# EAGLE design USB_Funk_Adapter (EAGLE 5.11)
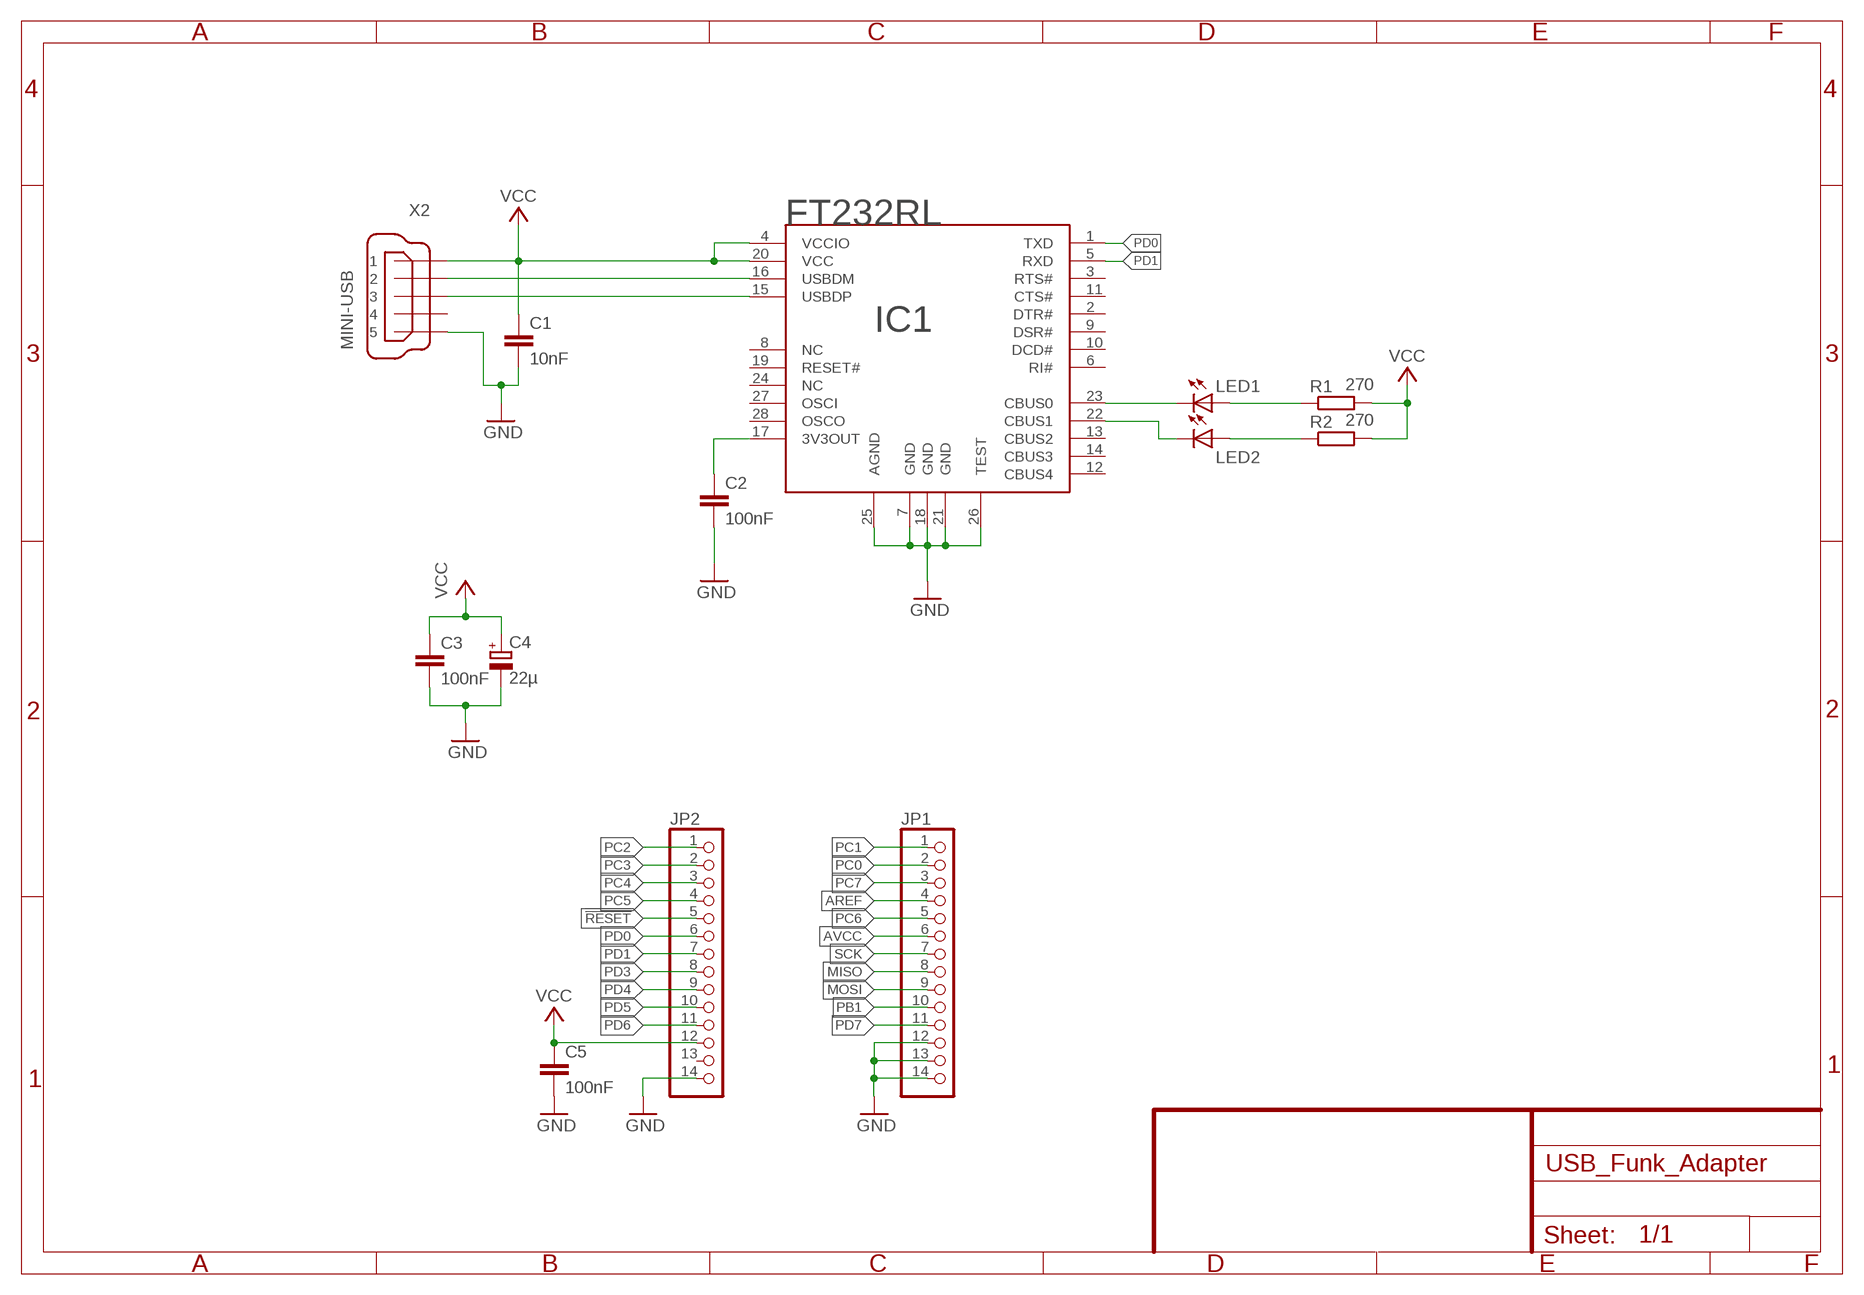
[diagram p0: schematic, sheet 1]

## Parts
C1  10nF  C-EUC0805  [C0805]
C2  100nF  C-EUC0805  [C0805]
C3  100nF  C-EUC0805  [C0805]
C4  22µ  CPOL-EU085CS-1AR  [085CS_1AR]
C5  100nF  C-EUC0805  [C0805]
IC1  FT232RL  [SSOP28]
JP1  PINHD-1X14  [1X14]
JP2  PINHD-1X14  [1X14]
LED1  LEDCHIPLED_0805  [CHIPLED_0805]
LED2  LEDCHIPLED_0805  [CHIPLED_0805]
R1  270  R-EU_R0805  [R0805]
R2  270  R-EU_R0805  [R0805]
X2  MINI-USB  MINI-USB-UX60-MB-5ST  [UX60-MB-5ST]

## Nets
!RESET: JP2.5
AREF: JP1.4
AVCC: JP1.6
GND: C1.2 C2.2 C3.2 C4.- C5.2 IC1.7(GND) IC1.18(GND) IC1.21(GND) IC1.25(AGND) IC1.26(TEST) JP1.12 JP1.13 JP1.14 JP2.14 X2.5
MISO: JP1.8
MOSI: JP1.9
N$1: IC1.16(USBDM) X2.2
N$2: IC1.15(USBDP) X2.3
N$5: C2.1 IC1.17(3V3OUT)
N$7: IC1.23(CBUS0) LED1.C
N$8: IC1.22(CBUS1) LED2.C
N$9: LED1.A R1.1
N$10: LED2.A R2.1
PB1: JP1.10
PC0: JP1.2
PC1: JP1.1
PC2: JP2.1
PC3: JP2.2
PC4: JP2.3
PC5: JP2.4
PC6: JP1.5
PC7: JP1.3
PD0: IC1.1(TXD) JP2.6
PD1: IC1.5(RXD) JP2.7
PD3: JP2.8
PD4: JP2.9
PD5: JP2.10
PD6: JP2.11
PD7: JP1.11
SCK: JP1.7
VCC: C1.1 C3.1 C4.+ C5.1 IC1.4(VCCIO) IC1.20(VCC) JP2.12 R1.2 R2.2 X2.1
Unconnected: IC1.2(DTR#) IC1.3(RTS#) IC1.6(RI#) IC1.8(NC) IC1.9(DSR#) IC1.10(DCD#) IC1.11(CTS#) IC1.12(CBUS4) IC1.13(CBUS2) IC1.14(CBUS3) IC1.19(RESET#) IC1.24(NC) IC1.27(OSCI) IC1.28(OSCO) JP2.13 X2.4

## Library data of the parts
C1-C3 C5 = rcl:C-EU: CAPACITOR, European symbol
C4 = rcl:CPOL-EU: POLARIZED CAPACITOR, European symbol
IC1 = FTDI:FT232RL
JP1 JP2 = pinhead:PINHD-1X14: PIN HEADER
LED1 LED2 = led:LED: LED
R1 R2 = rcl:R-EU_: RESISTOR, European symbol
X2 = con-hirose:MINI-USB-: MINI USB Connector Source: http://www.hirose.co.jp/cataloge_hp/e24000019.pdf; OC_FARNELL: unknown; OC_NEWARK: unknown

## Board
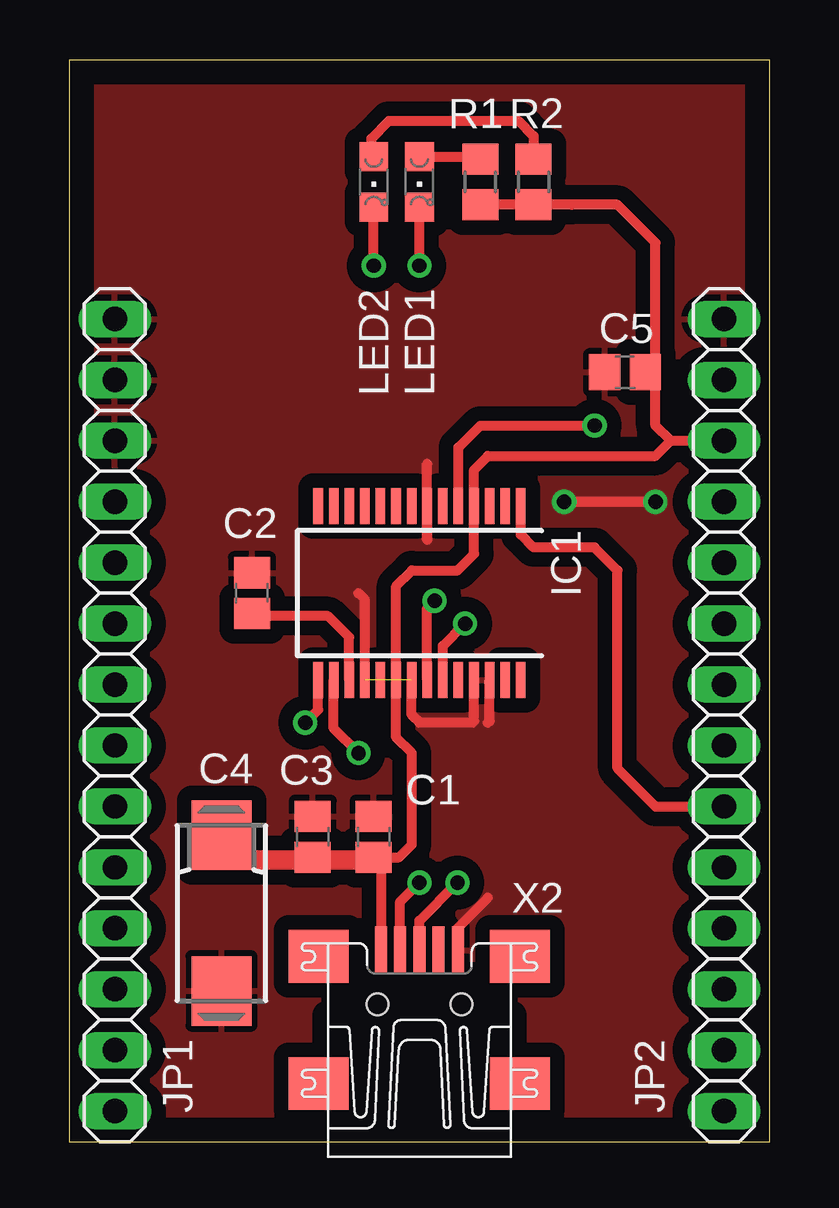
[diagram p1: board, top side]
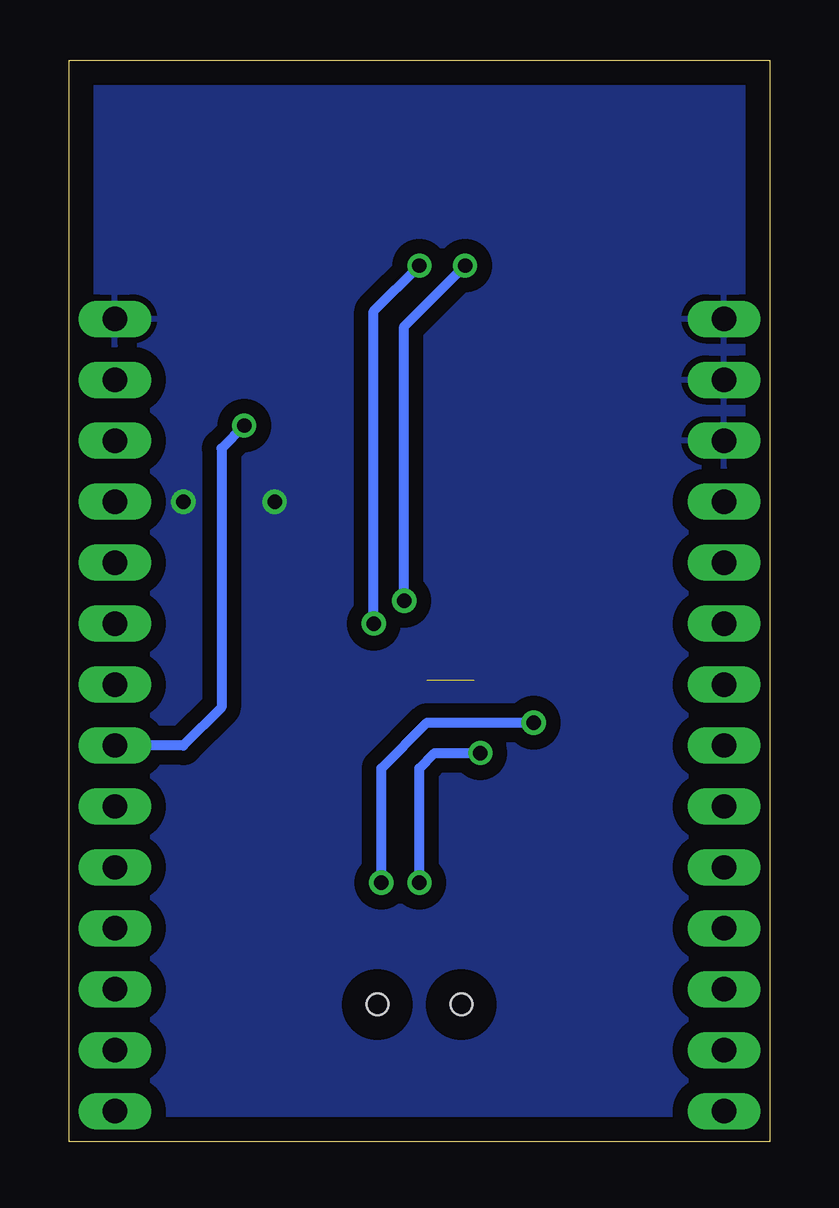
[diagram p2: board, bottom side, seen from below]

Size 29.21 x 45.09 mm. Coordinates in mm from the lower left corner, seen from the top.
Outline: 0,0 29.21,0 29.21,45.09 0,45.09 0,0
Copper layers (1*16): Top 0.035mm / dielectric 1.5mm / Bottom 0.035mm
Design rules "default": minimum track width 10mil, minimum drill 24mil, track to track 8mil, track to pad 8mil, pad to pad 8mil, via to via 8mil, smd to smd 8mil, copper to edge 40mil, drill to drill 8mil, minimum pad ring 10mil, minimum via ring 8mil, stop-mask expansion 4mil, vias tented up to drill 0mil, thermal gap 10mil

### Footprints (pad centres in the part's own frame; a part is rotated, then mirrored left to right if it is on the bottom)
C0805 = smd 1.3 x 1.5: 1 -0.85,0; 2 0.85,0
085CS_1AR = smd 2.9 x 2.5: + 3.25,0; - -3.25,0
SSOP28 = smd 0.4 x 1.5: 1 -4.225,-3.625; 2 -3.575,-3.625; 3 -2.925,-3.625; 4 -2.275,-3.625; 5 -1.625,-3.625; 6 -0.975,-3.625; 7 -0.325,-3.625; 8 0.325,-3.625; 9 0.975,-3.625; 10 1.625,-3.625; 11 2.275,-3.625; 12 2.925,-3.625; 13 3.575,-3.625; 14 4.225,-3.625; 15 4.225,3.625; 16 3.575,3.625; 17 2.925,3.625; 18 2.275,3.625; 19 1.625,3.625; 20 0.975,3.625; 21 0.325,3.625; 22 -0.325,3.625; 23 -0.975,3.625; 24 -1.625,3.625; 25 -2.275,3.625; 26 -2.925,3.625; 27 -3.575,3.625; 28 -4.225,3.625
1X14 = drill 1.016 long: 1 -16.51,0; 2 -13.97,0; 3 -11.43,0; 4 -8.89,0; 5 -6.35,0; 6 -3.81,0; 7 -1.27,0; 8 1.27,0; 9 3.81,0; 10 6.35,0; 11 8.89,0; 12 11.43,0; 13 13.97,0; 14 16.51,0
CHIPLED_0805 = smd 1.2 x 1.2: A 0,-1.05; C 0,1.05
R0805 = smd 1.3 x 1.5: 1 -0.95,0; 2 0.95,0
UX60-MB-5ST = smd 2 x 0.5: 1 2.25,1.6; 2 2.25,0.8; 3 2.25,0; 4 2.25,-0.8; 5 2.25,-1.6 | smd 2.2 x 2.5: M1 -3.3,-4.2; M2 -3.3,4.2; M3 2,4.2; M4 2,-4.2 | hole 0.9: 0,-1.75; 0,1.75

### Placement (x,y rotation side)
C1  12.7,12.7 90 top
C2  7.62,22.86 90 top
C3  10.16,12.7 90 top
C4  6.35,9.53 90 top
C5  23.18,32.07 180 top
IC1  14.6,22.86 180 top
JP1  1.91,17.78 90 top
JP2  27.3,17.78 90 top
LED1  14.6,40.01 180 top
LED2  12.7,40.01 180 top
R1  17.14,40.01 270 top
R2  19.37,40.01 270 top
X2  14.6,5.71 90 top

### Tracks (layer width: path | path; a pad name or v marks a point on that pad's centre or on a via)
GND  (via drill 0.6)  (1 unrouted)
  Top 0.406: X2.5 16.21,8.9 17.46,10.16 | IC1.26 17.53,17.53 17.46,17.46 | IC1.25 16.88,17.52 16.83,17.46 14.6,17.46 14.28,17.79 IC1.21 | IC1.7 14.93,25.09 14.92,25.08 14.92,28.26 | IC1.18 12.33,22.59 12.06,22.86 | v20.64,26.67 v24.45,26.67
  pour Bottom (isolate 0.61): 0,45.09 29.21,45.09 29.21,0 0,0
  pour Top (isolate 0.61): 0,45.09 29.21,45.09 29.21,0 0,0
N$1  (via drill 0.6)
  Top 0.406: X2.2 13.8,9.99 v14.6,10.79 | IC1.16 11.03,17.23 v12.06,16.19
  Bottom 0.406: v14.6,10.79 14.6,15.56 13.97,16.19 v12.06,16.19
N$2  (via drill 0.6)
  Top 0.406: X2.3 14.6,9.21 v16.19,10.79 | IC1.15 10.38,18 v9.84,17.46
  Bottom 0.406: v16.19,10.79 16.19,15.56 14.29,17.46 v9.84,17.46
N$5
  Top 0.406: IC1.17 11.68,21.02 10.79,21.91 7.72,21.91 C2.1
N$7  (via drill 0.6)
  Top 0.406: IC1.23 15.58,20.66 v16.51,21.59 | v14.6,36.51 LED1.C
  Bottom 0.406: v16.51,21.59 16.51,34.61 v14.6,36.51
N$8  (via drill 0.6)
  Top 0.406: IC1.22 14.93,22.23 v15.24,22.54 | v12.7,36.51 LED2.C
  Bottom 0.406: v15.24,22.54 15.24,33.97 v12.7,36.51
N$9
  Top 0.406: LED1.A 17.05,41.05 R1.1
N$10
  Top 0.406: LED2.A 12.6,40.96 12.6,41.81 13.33,42.55 18.73,42.55 19.37,41.91 R2.1
PD0
  Top 0.406: JP2.6 24.45,13.97 22.86,15.56 22.86,23.81 21.91,24.77 19.37,24.77 18.83,25.3 IC1.1
PD1  (via drill 0.6)
  Top 0.406: IC1.5 16.23,28.93 17.14,29.84 v21.91,29.84
  Bottom 0.406: v21.91,29.84 22.86,28.89 22.86,18.1 24.45,16.51 JP2.7
VCC
  Top 0.406: C4.+ 6.99,12.78 6.99,11.75 | 10.16,11.75 C3.1 | 12.7,11.75 C1.1 | X2.1 13,11.54 C1.1 | C1.1 13.75,11.85 14.29,12.38 14.29,16.19 13.63,16.85 IC1.20 13.63,23.16 14.29,23.81 16.19,23.81 16.88,24.5 IC1.4 16.88,27.99 17.46,28.57 24.45,28.57 25.08,29.21 | R1.2 R2.2 20.96,39.05 22.86,39.05 24.45,37.47 24.45,31.65 | 25.08,29.21 24.45,29.84 24.45,31.65 | 25.08,29.21 JP2.12 | 24.45,31.65 C5.1
  Top 0.813: 6.99,11.75 10.16,11.75 12.7,11.75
